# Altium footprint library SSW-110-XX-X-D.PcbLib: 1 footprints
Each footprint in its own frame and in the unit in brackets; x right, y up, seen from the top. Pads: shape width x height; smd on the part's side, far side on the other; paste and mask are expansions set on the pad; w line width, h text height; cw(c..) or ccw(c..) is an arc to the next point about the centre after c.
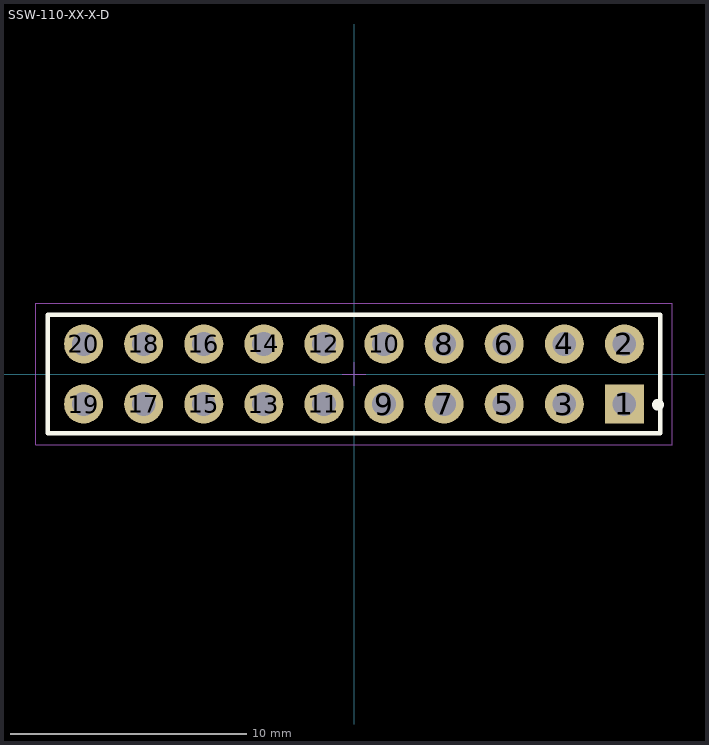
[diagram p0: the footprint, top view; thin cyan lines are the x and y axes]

## SSW-110-XX-X-D [mm] "2.54mm pitch, 20 pin, socket strip; double row"
height 8.51
pads (20):
  rect 1.65x1.65 / inner round 1.65 / far side rect 1.65x1.65 hole 1 mask+0: 1(11.43,-1.27)
  round 1.65 hole 1 mask+0: 2(11.43,1.27) 3(8.89,-1.27) 4(8.89,1.27) 5(6.35,-1.27) 6(6.35,1.27) 7(3.81,-1.27) 8(3.81,1.27) 9(1.27,-1.27) 10(1.27,1.27) 11(-1.27,-1.27) 12(-1.27,1.27) 13(-3.81,-1.27) 14(-3.81,1.27) 15(-6.35,-1.27) 16(-6.35,1.27) 17(-8.89,-1.27) 18(-8.89,1.27) 19(-11.43,-1.27) 20(-11.43,1.27)
Top Overlay:
  circle w0.25: c12.85,-1.3 r0.125
  lines w0.2: -12.95,-2.5 12.95,-2.5 12.95,2.5 -12.95,2.5 -12.95,-2.5
Mechanical 12:
  lines w0.001: -12.95,-2.5 12.95,-2.5 12.95,2.5 -12.95,2.5 -12.95,-2.5
Mechanical 13:
  lines w0.1: -12.95,-2.5 12.95,-2.5 12.95,2.5 -12.95,2.5 -12.95,-2.5
  text ".Designator" at 0,-0.127 h1.52
Mechanical 15:
  lines w0.05: -0.5,0 0.5,0 ; 0,-0.5 0,0.5 ; -13.45,-3 13.45,-3 13.45,3 -13.45,3 -13.45,-3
